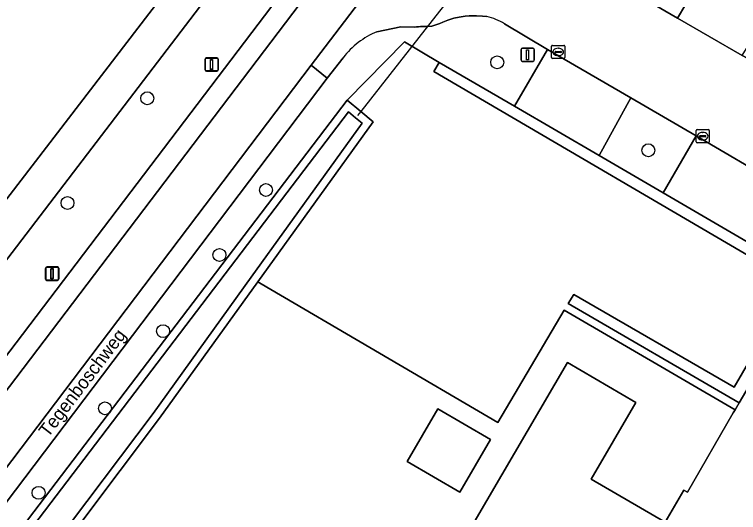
# Model space of a CAD drawing. Extents: x 156502 to 159075, y 384229 to 386100.
# Drawn here: x 157051.2 to 157106.1, y 385862.3 to 385900 of the extents above; entities that cross this region are included whole.
import ezdxf

# ---------------------------------------------------------------- set-up
doc = ezdxf.new("R2010")
doc.units = 0
for name, color, linetype in [('IMGEO_Berm_groen', 7, 'Continuous'), ('IMGEO_Berm_halfverhard', 7, 'Continuous'), ('IMGEO_Boom', 7, 'Continuous'), ('IMGEO_Duiker', 7, 'Continuous'), ('IMGEO_Erf', 7, 'Continuous'), ('IMGEO_Groenvoorziening', 7, 'Continuous'), ('IMGEO_Haag', 7, 'Continuous'), ('IMGEO_Hek', 7, 'Continuous'), ('IMGEO_Kolk', 7, 'Continuous'), ('IMGEO_Lichtmast', 7, 'Continuous'), ('IMGEO_Oever', 7, 'Continuous'), ('IMGEO_Openbare_ruimte_label', 7, 'Continuous'), ('IMGEO_Pand', 7, 'Continuous'), ('IMGEO_Parkeervlak_open', 7, 'Continuous'), ('IMGEO_Rijbaan_lokaal_gesloten', 7, 'Continuous'), ('IMGEO_Voetpad_open', 7, 'Continuous'), ('IMGEO_Waterloop', 7, 'Continuous')]:
    doc.layers.add(name, color=color, linetype=linetype)

msp = doc.modelspace()

# ---------------------------------------------------------------- linework, layer by layer
at = {"layer": 'IMGEO_Berm_groen'}
for points in [[(157188.566, 386055.162), (157184.907, 386057.234), (157021.918, 385843.894)], [(157027.777, 385843.918), (157039.623, 385859.739), (157076.319, 385908.026), (157188.566, 386055.162)]]:
    msp.add_lwpolyline(points, dxfattribs=at)
for points in [[(157108.945, 385901.089), (157104.008, 385904.025), (157101.482, 385899.753), (157106.365, 385896.913)], [(157102.881, 385890.842), (157097.95, 385893.707), (157095.538, 385889.341), (157100.401, 385886.518)]]:
    msp.add_lwpolyline(points, close=True, dxfattribs=at)
at = {"layer": 'IMGEO_Berm_halfverhard'}
for points in [[(157028.972, 385842.844), (157041.694, 385859.803), (157077.656, 385907.175), (157189.916, 386054.397), (157188.566, 386055.162), (157076.319, 385908.026), (157039.623, 385859.739), (157027.777, 385843.918), (157027.693, 385843.804)], [(157074.946, 385895.192), (157073.728, 385896.192), (157041.03, 385853.045), (157032.276, 385841.324)], [(157031.66, 385840.505), (157032.855, 385839.465), (157043.149, 385853.233), (157074.946, 385895.192)]]:
    msp.add_lwpolyline(points, dxfattribs=at)
at = {"layer": 'IMGEO_Boom'}
for centre in [(157087.82, 385896.404), (157061.306, 385893.682), (157099.272, 385889.744), (157070.302, 385886.733), (157055.263, 385885.754), (157066.776, 385881.815), (157062.506, 385876.047), (157058.102, 385870.199), (157053.074, 385863.804)]:
    msp.add_circle(centre, 0.489, dxfattribs=at)
at = {"layer": 'IMGEO_Duiker'}
msp.add_lwpolyline([(157094.166, 385913.916), (157093.864, 385913.531), (157090.745, 385909.563), (157082.608, 385899.211), (157077.479, 385892.687), (157077.23, 385892.37)], dxfattribs=at)
at = {"layer": 'IMGEO_Erf'}
msp.add_lwpolyline([(157106.562, 385858.084), (157102.808, 385851.646), (157093.53, 385857.04), (157093.801, 385857.507), (157091.477, 385858.867), (157091.192, 385858.41), (157086.085, 385861.587), (157093.153, 385873.673), (157098.324, 385870.649), (157094.927, 385864.842), (157100.545, 385861.579), (157101.95, 385864.014), (157102.227, 385863.854), (157105.698, 385869.85), (157105.837, 385870.09), (157092.904, 385877.624), (157087.856, 385869.139), (157069.928, 385879.631), (157069.688, 385879.771), (157062.244, 385869.451), (157047.224, 385849.55)], dxfattribs=at)
msp.add_lwpolyline([(157080.994, 385866.183), (157083.323, 385870.166), (157087.307, 385867.836), (157084.978, 385863.853)], close=True, dxfattribs=at)
at = {"layer": 'IMGEO_Groenvoorziening'}
for points in [[(157021.918, 385843.894), (157184.907, 386057.234), (157182.471, 386058.613), (157155.614, 386073.823), (157152.797, 386073.936)], [(157180.634, 386056.206), (157071.087, 385912.699), (157029.054, 385857.935), (157019.844, 385845.786), (157020.691, 385844.872)], [(157087.034, 385899.877), (157086.696, 385899.895), (157086.259, 385899.926), (157085.687, 385899.926), (157085.387, 385899.9), (157084.936, 385899.83), (157084.526, 385899.739), (157084.083, 385899.599), (157083.705, 385899.44), (157083.46, 385899.336), (157082.877, 385899.153), (157082.528, 385899.11), (157082.003, 385899.108), (157081.857, 385899.092), (157081.711, 385899.078), (157081.564, 385899.068), (157080.51, 385899.085), (157078.711, 385898.72)], [(157044.158, 385787.921), (157048.506, 385785.444), (157045.399, 385797.293), (157042.738, 385795.688), (157037.896, 385808.02), (157032.23, 385821.835), (157031.084, 385827.859), (157030.83, 385829.194), (157033.907, 385837.957), (157049.627, 385858.357), (157076.448, 385893.546), (157080.786, 385897.944), (157083.416, 385896.387), (157089.134, 385893.087), (157091.625, 385897.383), (157088.378, 385899.319)], [(157076.145, 385896.75), (157074.946, 385895.192), (157043.149, 385853.233), (157032.855, 385839.465)]]:
    msp.add_lwpolyline(points, dxfattribs=at)
for points in [[(157180.634, 386056.206), (157157.667, 386069.213), (157141.859, 386060.718), (157119.898, 386031.613), (157112.225, 386027.38), (157100.054, 386012.563), (157083.49, 386002.815), (157074.431, 385999.041), (157069.734, 385990.233), (157066.45, 385980.334), (157048.46, 385958.059), (157049.783, 385948.534), (157024.383, 385917.578), (157012.477, 385911.492), (157001.337, 385911.378), (156999.468, 385912.632), (156989.301, 385898.643), (156990.12, 385896.678), (157010.156, 385862.563), (157019.003, 385846.692), (157019.844, 385845.786), (157029.054, 385857.935), (157071.087, 385912.699)], [(157083.012, 385895.697), (157083.416, 385896.387), (157080.786, 385897.944), (157076.448, 385893.546), (157077.479, 385892.687), (157078.432, 385891.893), (157069.688, 385879.771), (157069.928, 385879.631), (157087.856, 385869.139), (157092.904, 385877.624), (157105.837, 385870.09), (157106.141, 385870.607), (157093.206, 385878.142), (157093.618, 385878.818), (157105.763, 385871.809), (157110.374, 385879.708)], [(157106.766, 385882.82), (157100.401, 385886.518), (157095.538, 385889.341), (157089.134, 385893.087), (157083.416, 385896.387), (157083.012, 385895.697), (157110.374, 385879.708), (157105.763, 385871.809), (157093.618, 385878.818), (157093.206, 385878.142), (157106.141, 385870.607), (157111.651, 385879.994)]]:
    msp.add_lwpolyline(points, close=True, dxfattribs=at)
for centre, radius, start, end in [((157085.798, 385895.003), 5.028, 59.1326, 75.773), ((157081.05, 385893.017), 6.164, 112.3007, 142.7285)]:
    msp.add_arc(centre, radius, start, end, dxfattribs=at)
at = {"layer": 'IMGEO_Haag'}
msp.add_lwpolyline([(157106.766, 385882.82), (157100.401, 385886.518), (157095.538, 385889.341), (157089.134, 385893.087), (157083.416, 385896.387), (157083.012, 385895.697), (157110.374, 385879.708), (157105.763, 385871.809), (157093.618, 385878.818), (157093.206, 385878.142), (157106.141, 385870.607), (157111.651, 385879.994)], close=True, dxfattribs=at)
at = {"layer": 'IMGEO_Hek'}
for points in [[(157069.928, 385879.631), (157069.688, 385879.771)], [(157105.837, 385870.09), (157092.904, 385877.624), (157087.856, 385869.139), (157069.928, 385879.631)], [(157101.95, 385864.014), (157102.227, 385863.854), (157105.698, 385869.85)], [(157105.698, 385869.85), (157105.837, 385870.09)], [(157062.244, 385869.451), (157047.224, 385849.55)]]:
    msp.add_lwpolyline(points, dxfattribs=at)
at = {"layer": 'IMGEO_Kolk'}
for p, q in [((157092.018, 385897.688), (157092.87, 385897.688)), ((157091.943, 385896.762), (157091.943, 385897.614)), ((157092.202, 385897.182), (157092.202, 385897.194)), ((157092.64, 385897.145), (157092.242, 385897.145)), ((157092.245, 385897.231), (157092.643, 385897.231)), ((157092.431, 385897.468), (157092.456, 385897.468)), ((157092.686, 385897.194), (157092.686, 385897.182)), ((157092.944, 385897.614), (157092.944, 385896.762)), ((157092.87, 385896.688), (157092.018, 385896.688)), ((157092.454, 385896.908), (157092.429, 385896.908)), ((157102.888, 385890.384), (157102.888, 385891.236)), ((157102.963, 385891.31), (157103.815, 385891.31)), ((157103.889, 385891.236), (157103.889, 385890.384)), ((157103.147, 385890.804), (157103.147, 385890.816)), ((157103.585, 385890.767), (157103.187, 385890.767)), ((157103.19, 385890.853), (157103.588, 385890.853)), ((157103.376, 385891.09), (157103.401, 385891.09)), ((157103.631, 385890.816), (157103.631, 385890.804)), ((157103.815, 385890.31), (157102.963, 385890.31)), ((157103.399, 385890.53), (157103.374, 385890.53))]:
    msp.add_line(p, q, dxfattribs=at)
for points in [[(157092.018, 385897.688), (157092.87, 385897.688)], [(157091.943, 385896.762), (157091.943, 385897.614)], [(157092.944, 385897.614), (157092.944, 385896.762)], [(157092.87, 385896.688), (157092.018, 385896.688)], [(157102.888, 385890.384), (157102.888, 385891.236)], [(157102.963, 385891.31), (157103.815, 385891.31)], [(157103.889, 385891.236), (157103.889, 385890.384)], [(157103.815, 385890.31), (157102.963, 385890.31)]]:
    msp.add_lwpolyline(points, dxfattribs=at)
for centre, radius, start, end in [((157092.02, 385897.612), 0.0765, 91.552, 178.448), ((157092.02, 385897.612), 0.0765, 91.552, 178.448), ((157092.868, 385897.612), 0.0765, 1.552, 88.448), ((157092.868, 385897.612), 0.0765, 1.552, 88.448), ((157092.242, 385897.191), 0.0403, 85.8775, 175.7526), ((157092.239, 385897.181), 0.0366, 178.938, 274.7102), ((157092.643, 385897.188), 0.043, 264.8664, 352.4533), ((157092.647, 385897.193), 0.0386, 1.7309, 96.639), ((157092.02, 385896.764), 0.0765, 181.552, 268.448), ((157092.02, 385896.764), 0.0765, 181.552, 268.448), ((157092.868, 385896.764), 0.0765, 271.552, 358.448), ((157092.868, 385896.764), 0.0765, 271.552, 358.448), ((157102.965, 385891.234), 0.0765, 91.552, 178.448), ((157102.965, 385891.234), 0.0765, 91.552, 178.448), ((157103.813, 385891.234), 0.0765, 1.552, 88.448), ((157103.813, 385891.234), 0.0765, 1.552, 88.448), ((157103.187, 385890.813), 0.0403, 85.8775, 175.7526), ((157103.184, 385890.803), 0.0366, 178.938, 274.7102), ((157103.588, 385890.81), 0.043, 264.8664, 352.4533), ((157103.592, 385890.815), 0.0386, 1.7309, 96.639), ((157102.965, 385890.386), 0.0765, 181.552, 268.448), ((157102.965, 385890.386), 0.0765, 181.552, 268.448), ((157103.813, 385890.386), 0.0765, 271.552, 358.448), ((157103.813, 385890.386), 0.0765, 271.552, 358.448)]:
    msp.add_arc(centre, radius, start, end, dxfattribs=at)
for centre, major_axis, ratio, start_param, end_param in [((157092.43, 385897.188), (-0.387, 0.002), 0.722429, 4.712389, 7.853982), ((157092.455, 385897.188), (-0.39, 0.002), 0.717154, 1.570796, 4.712389), ((157103.375, 385890.81), (-0.387, 0.002), 0.722429, 4.712389, 7.853982), ((157103.4, 385890.81), (-0.39, 0.002), 0.717154, 1.570796, 4.712389)]:
    msp.add_ellipse(centre, major_axis=major_axis, ratio=ratio, start_param=start_param, end_param=end_param, dxfattribs=at)
at = {"layer": 'IMGEO_Lichtmast'}
for p, q in [((157089.623, 385896.575), (157089.623, 385897.375)), ((157089.623, 385897.375), (157089.623, 385896.575)), ((157089.723, 385897.475), (157090.513, 385897.475)), ((157090.513, 385897.475), (157089.723, 385897.475)), ((157090.613, 385897.375), (157090.613, 385896.575)), ((157090.613, 385896.575), (157090.613, 385897.375)), ((157065.682, 385895.85), (157065.682, 385896.65)), ((157065.682, 385896.65), (157065.682, 385895.85)), ((157065.688, 385895.822), (157065.688, 385896.622)), ((157065.688, 385896.622), (157065.688, 385895.822)), ((157065.782, 385896.75), (157066.572, 385896.75)), ((157066.572, 385896.75), (157065.782, 385896.75)), ((157065.788, 385896.722), (157066.578, 385896.722)), ((157066.578, 385896.722), (157065.788, 385896.722)), ((157066.672, 385896.65), (157066.672, 385895.85)), ((157066.672, 385895.85), (157066.672, 385896.65)), ((157066.678, 385896.622), (157066.678, 385895.822)), ((157066.678, 385895.822), (157066.678, 385896.622)), ((157090.513, 385896.475), (157089.723, 385896.475)), ((157089.723, 385896.475), (157090.513, 385896.475)), ((157066.572, 385895.75), (157065.782, 385895.75)), ((157065.782, 385895.75), (157066.572, 385895.75)), ((157066.578, 385895.722), (157065.788, 385895.722)), ((157065.788, 385895.722), (157066.578, 385895.722)), ((157053.593, 385879.991), (157053.593, 385880.791)), ((157053.593, 385880.791), (157053.593, 385879.991)), ((157053.619, 385880.007), (157053.619, 385880.807)), ((157053.619, 385880.807), (157053.619, 385880.007)), ((157053.693, 385880.891), (157054.483, 385880.891)), ((157054.483, 385880.891), (157053.693, 385880.891)), ((157053.719, 385880.907), (157054.509, 385880.907)), ((157054.509, 385880.907), (157053.719, 385880.907)), ((157054.583, 385880.791), (157054.583, 385879.991)), ((157054.583, 385879.991), (157054.583, 385880.791)), ((157054.609, 385880.807), (157054.609, 385880.007)), ((157054.609, 385880.007), (157054.609, 385880.807)), ((157054.483, 385879.891), (157053.693, 385879.891)), ((157053.693, 385879.891), (157054.483, 385879.891)), ((157054.509, 385879.907), (157053.719, 385879.907)), ((157053.719, 385879.907), (157054.509, 385879.907))]:
    msp.add_line(p, q, dxfattribs=at)
for points in [[(157090.043, 385897.35), (157090.193, 385897.35), (157090.193, 385896.6), (157090.043, 385896.6), (157090.043, 385897.35)], [(157066.102, 385896.625), (157066.252, 385896.625), (157066.252, 385895.875), (157066.102, 385895.875), (157066.102, 385896.625)], [(157066.108, 385896.597), (157066.258, 385896.597), (157066.258, 385895.847), (157066.108, 385895.847), (157066.108, 385896.597)], [(157054.013, 385880.766), (157054.163, 385880.766), (157054.163, 385880.016), (157054.013, 385880.016), (157054.013, 385880.766)], [(157054.039, 385880.782), (157054.189, 385880.782), (157054.189, 385880.032), (157054.039, 385880.032), (157054.039, 385880.782)]]:
    msp.add_lwpolyline(points, dxfattribs=at)
for centre, start, end in [((157089.723, 385897.375), 90, 180), ((157089.723, 385897.375), 90, 180), ((157090.513, 385897.375), 0, 90), ((157090.513, 385897.375), 360, 90), ((157065.782, 385896.65), 90, 180), ((157065.782, 385896.65), 90, 180), ((157065.788, 385896.622), 90, 180), ((157065.788, 385896.622), 90, 180), ((157066.572, 385896.65), 0, 90), ((157066.572, 385896.65), 360, 90), ((157066.578, 385896.622), 0, 90), ((157066.578, 385896.622), 360, 90), ((157089.723, 385896.575), 180, 270), ((157089.723, 385896.575), 180, 270), ((157090.513, 385896.575), 270, 0), ((157090.513, 385896.575), 270, 0), ((157065.782, 385895.85), 180, 270), ((157065.782, 385895.85), 180, 270), ((157065.788, 385895.822), 180, 270), ((157065.788, 385895.822), 180, 270), ((157066.572, 385895.85), 270, 0), ((157066.572, 385895.85), 270, 0), ((157066.578, 385895.822), 270, 0), ((157066.578, 385895.822), 270, 0), ((157053.693, 385880.791), 90, 180), ((157053.693, 385880.791), 90, 180), ((157053.719, 385880.807), 90, 180), ((157053.719, 385880.807), 90, 180), ((157054.483, 385880.791), 0, 90), ((157054.483, 385880.791), 360, 90), ((157054.509, 385880.807), 0, 90), ((157054.509, 385880.807), 360, 90), ((157053.693, 385879.991), 180, 270), ((157053.693, 385879.991), 180, 270), ((157053.719, 385880.007), 180, 270), ((157053.719, 385880.007), 180, 270), ((157054.483, 385879.991), 270, 0), ((157054.483, 385879.991), 270, 0), ((157054.509, 385880.007), 270, 0), ((157054.509, 385880.007), 270, 0)]:
    msp.add_arc(centre, 0.1, start, end, dxfattribs=at)
at = {"layer": 'IMGEO_Oever'}
for points in [[(157076.448, 385893.546), (157049.627, 385858.357), (157033.907, 385837.957), (157030.83, 385829.194), (157031.084, 385827.859), (157032.23, 385821.835), (157037.896, 385808.02), (157042.738, 385795.688), (157045.399, 385797.293), (157034.848, 385824.224)], [(157036.041, 385834.964), (157036.588, 385835.458), (157041.356, 385841.775), (157064.372, 385828.327), (157172.677, 385766.006), (157173.435, 385767.228), (157068.346, 385827.983), (157065.314, 385829.887), (157042.786, 385843.67), (157047.224, 385849.55), (157062.244, 385869.451), (157069.688, 385879.771), (157078.432, 385891.893), (157077.479, 385892.687), (157076.448, 385893.546)], [(157050.121, 385857.979), (157076.549, 385892.652), (157077.081, 385892.209), (157077.588, 385891.786), (157069.183, 385880.135), (157061.743, 385869.82), (157046.727, 385849.925)]]:
    msp.add_lwpolyline(points, dxfattribs=at)
at = {"layer": 'IMGEO_Pand'}
for points in [[(157100.836, 385861.41), (157100.545, 385861.579), (157094.927, 385864.842), (157098.324, 385870.649), (157093.153, 385873.673), (157086.085, 385861.587), (157091.192, 385858.41), (157091.477, 385858.867), (157093.801, 385857.507), (157093.53, 385857.04), (157102.808, 385851.646), (157106.562, 385858.084)], [(157080.994, 385866.183), (157084.978, 385863.853), (157087.307, 385867.836), (157083.323, 385870.166)]]:
    msp.add_lwpolyline(points, close=True, dxfattribs=at)
at = {"layer": 'IMGEO_Parkeervlak_open'}
for points in [[(157101.482, 385899.753), (157104.008, 385904.025), (157097.842, 385907.574), (157095.28, 385903.36)], [(157091.625, 385897.383), (157089.134, 385893.087), (157095.538, 385889.341), (157097.95, 385893.707)], [(157102.881, 385890.842), (157100.401, 385886.518), (157106.766, 385882.82), (157109.179, 385887.161)]]:
    msp.add_lwpolyline(points, close=True, dxfattribs=at)
at = {"layer": 'IMGEO_Rijbaan_lokaal_gesloten'}
for points in [[(157170.869, 386020.883), (157170.373, 386022.922), (157193.363, 386053.168), (157195.745, 386055.945), (157192.084, 386057.732), (157191.18, 386056.232), (157189.916, 386054.397), (157077.656, 385907.175), (157041.694, 385859.803), (157028.972, 385842.844), (157031.66, 385840.505)], [(157032.276, 385841.324), (157041.03, 385853.045), (157073.728, 385896.192), (157090.505, 385918.168)], [(157090.823, 385915.946), (157091.656, 385917.037), (157091.358, 385917.289), (157091.493, 385917.48), (157090.505, 385918.168), (157073.728, 385896.192), (157074.946, 385895.192), (157076.145, 385896.75)], [(157119.669, 385889.108), (157117.68, 385890.28), (157112.736, 385893.192), (157106.365, 385896.913), (157101.482, 385899.753), (157095.28, 385903.36), (157092.517, 385905.001)], [(157078.711, 385898.72), (157080.51, 385899.085), (157081.564, 385899.068), (157081.711, 385899.078), (157081.857, 385899.092), (157082.003, 385899.108), (157082.528, 385899.11), (157082.877, 385899.153), (157083.46, 385899.336), (157083.705, 385899.44), (157084.083, 385899.599), (157084.526, 385899.739), (157084.936, 385899.83), (157085.387, 385899.9), (157085.687, 385899.926), (157086.259, 385899.926), (157086.696, 385899.895), (157087.034, 385899.877)], [(157088.378, 385899.319), (157091.625, 385897.383), (157097.95, 385893.707), (157102.881, 385890.842), (157109.179, 385887.161), (157114.16, 385884.269), (157116.16, 385883.109)]]:
    msp.add_lwpolyline(points, dxfattribs=at)
for centre, radius, start, end in [((157085.798, 385895.003), 5.028, 59.1326, 75.773), ((157081.05, 385893.017), 6.164, 112.3007, 142.7285)]:
    msp.add_arc(centre, radius, start, end, dxfattribs=at)
at = {"layer": 'IMGEO_Voetpad_open'}
msp.add_lwpolyline([(157116.16, 385883.109), (157114.16, 385884.269), (157111.651, 385879.994), (157106.141, 385870.607), (157105.837, 385870.09), (157105.698, 385869.85), (157102.227, 385863.854), (157101.95, 385864.014), (157100.545, 385861.579), (157100.836, 385861.41), (157106.562, 385858.084), (157112.648, 385854.542), (157123.992, 385847.954), (157134.715, 385841.68), (157146.045, 385835.121), (157155.595, 385829.52), (157159.85, 385827.054), (157183.031, 385813.57)], dxfattribs=at)
at = {"layer": 'IMGEO_Waterloop'}
msp.add_lwpolyline([(157046.727, 385849.925), (157061.743, 385869.82), (157069.183, 385880.135), (157077.588, 385891.786), (157077.081, 385892.209), (157076.549, 385892.652), (157050.121, 385857.979)], dxfattribs=at)

# ---------------------------------------------------------------- texts
at = {"layer": 'IMGEO_Openbare_ruimte_label'}
msp.add_text('Tegenboschweg', height=1, rotation=52.5572, dxfattribs=at).set_placement((157053.796, 385867.938))

doc.saveas('drawing.dxf')
